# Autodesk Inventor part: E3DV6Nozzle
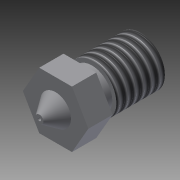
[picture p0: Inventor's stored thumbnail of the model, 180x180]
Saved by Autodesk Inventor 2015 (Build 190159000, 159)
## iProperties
Created: 2014-08
Part Number: E3DV6Nozzle
Material: Generic
Document SubType Name: Modeling
Designer: Jack
Density: 1 g/cm^3
Appearance: Default
Author: Jack
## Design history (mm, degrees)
sketch "Sketch1"
  geometry: L1 (0, 0)-(0.5, 0); L2 (0.5, 0)-(1.9, 2); L3 (1.9, 2)-(4.5, 2); L4 (4.5, 2)-(4.5, 5); L5 (4.5, 5)-(2.5, 5); L6 (2.5, 5)-(2.5, 6.5); L7 (2.5, 6.5)-(3, 6.5); L8 (3, 6.5)-(3, 12.5); L9 (3, 12.5)-(0, 12.5); L10 (0, 12.5)-(0, 0)
  constraints: 20 end point, 4 perpendicular, 3 vertical, 2 horizontal
  dimensions: "d0" = 0.5 distance of L1.start L1.end; "d1" = 125 deg angle of L1 L2; "d3" = 4.5 horizontal distance of L1.start L3.end; "d4" = 3 distance of L3.end L4.end; "d5" = 2.5 horizontal distance of L1.start L5.end; "d6" = 1.5 distance of L5.end L6.end; "d7" = 3 horizontal distance of L1.start L7.end; "d8" = 10.5 distance between parallel lines of L3 L9; "d9" = 12.5 distance between parallel lines of L1 L9
revolve "Revolution1" sketch "Sketch1" stored, may be unused: angle "d10" = 90 deg
sketch "Sketch2"
  geometry: L1 (4.041, 0)-(2.021, -3.5); L2 (2.021, -3.5)-(-2.021, -3.5); L3 (-2.021, -3.5)-(-4.041, 0); L4 (-4.041, 0)-(-2.021, 3.5); L5 (-2.021, 3.5)-(2.021, 3.5); L6 (2.021, 3.5)-(4.041, 0); C1 r 4.5 at (0, 0) reference; 1 further point
  constraints: 12 end point, 1 coincident, 1 horizontal, 13 other
  dimensions: "d11" = 7 distance between parallel lines of L5 L2
extrude "Extrusion1" cut sketch "Sketch2" stored distance "d12" = 10; taper "d13" = 0 deg
thread "Thread1" dims "d14" = 10, "d15" = 0
sketch "Sketch3"
  geometry: C1 r 3 at (0, 0) reference; C2 r 1 at (0, 0)
  constraints: 1 centre point, 1 coincident
  dimensions: "d16" = 2 diameter of C2
extrude "Extrusion2" cut sketch "Sketch3" distance "d17" = 10.5; taper "d18" = 0 deg
sketch "Sketch4"
  geometry: C1 r 0.5 at (0, 0) reference; C2 r 0.2 at (0, 0)
  constraints: 1 centre point, 1 coincident
  dimensions: "d19" = 0.4 diameter of C2
extrude "Extrusion3" cut sketch "Sketch4" stored distance "d20" = 10.5; taper "d21" = 0 deg
body "Solid1"
